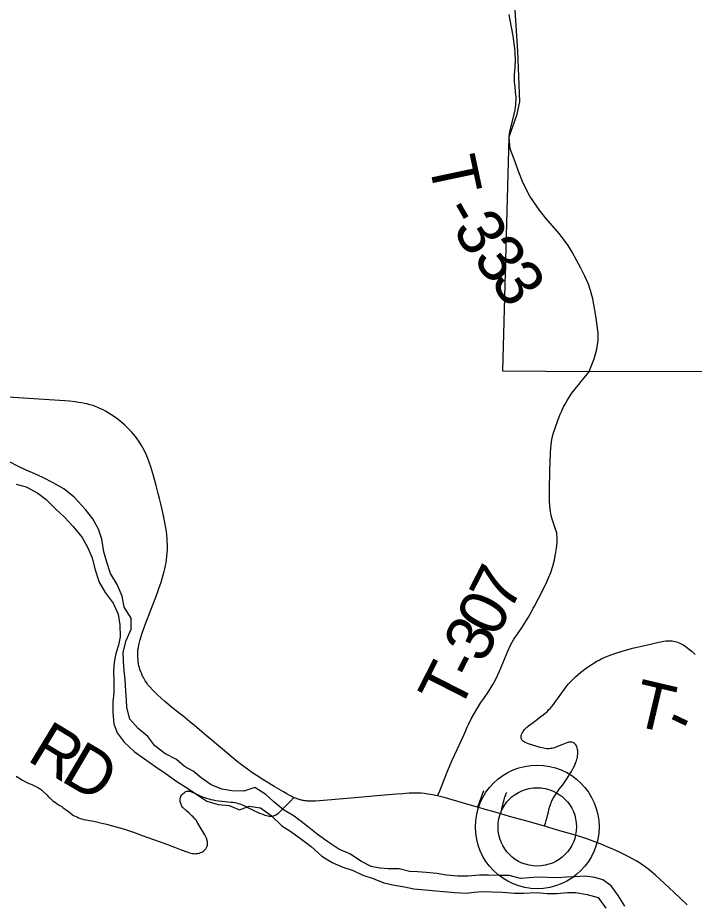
# Model space of a CAD drawing. Extents: x -10.5 to 40.6, y -3.2 to 22.
# Drawn here: x -9.859 to -9.045, y 17.758 to 18.823 of the extents above; entities that cross this region are included whole.
import ezdxf

# ---------------------------------------------------------------- set-up
doc = ezdxf.new("R2010")
doc.units = 0
for name, color, linetype in [('GM_X_Major_River', 7, 'Continuous'), ('GM_X_State_Route', 7, 'Continuous'), ('GM_X_Township_Road', 7, 'Continuous'), ('GM_X_Township_Road_Text', 7, 'Continuous'), ('GM_X_Township_Text', 7, 'Continuous'), ('GM_X_Unincorporated', 7, 'Continuous'), ('GM_X_Unincorporated_Location', 7, 'Continuous')]:
    doc.layers.add(name, color=color, linetype=linetype)

msp = doc.modelspace()

# ---------------------------------------------------------------- linework, layer by layer
at = {"layer": 'GM_X_Major_River'}
for points in [[(-9.1984, 17.7879), (-9.2086, 17.787), (-9.2215, 17.7876), (-9.2336, 17.7878), (-9.2439, 17.7869), (-9.2537, 17.7864), (-9.2674, 17.79), (-9.2776, 17.7898), (-9.2924, 17.7904), (-9.303, 17.7903), (-9.3171, 17.7889), (-9.3296, 17.7891), (-9.3428, 17.7901), (-9.3546, 17.7922), (-9.3675, 17.7936), (-9.3778, 17.7942), (-9.3873, 17.7948), (-9.3998, 17.7977), (-9.4131, 17.7979), (-9.4233, 17.7985), (-9.4336, 17.8006), (-9.4454, 17.8069), (-9.4592, 17.8158), (-9.4726, 17.8217), (-9.4859, 17.8303), (-9.4986, 17.8396), (-9.5128, 17.8508), (-9.5262, 17.8612), (-9.5392, 17.869), (-9.5507, 17.8787), (-9.5603, 17.8873), (-9.5737, 17.8958), (-9.5869, 17.8915), (-9.6013, 17.892), (-9.6134, 17.8938), (-9.6264, 17.8989), (-9.6383, 17.9075), (-9.6479, 17.9153), (-9.6585, 17.9212), (-9.6681, 17.9294), (-9.6819, 17.9368), (-9.6941, 17.9458), (-9.7026, 17.9574), (-9.7141, 17.9667), (-9.7242, 17.978), (-9.7278, 17.992), (-9.7283, 18.0014), (-9.7288, 18.012), (-9.7297, 18.0253), (-9.731, 18.0363), (-9.7319, 18.048), (-9.7321, 18.0587), (-9.7285, 18.0727), (-9.7226, 18.0865), (-9.7224, 18.0997), (-9.7309, 18.1129), (-9.7334, 18.1261), (-9.7396, 18.1401), (-9.7474, 18.1533), (-9.7517, 18.1669), (-9.7553, 18.1797), (-9.7578, 18.1948), (-9.7618, 18.2069), (-9.7688, 18.2193), (-9.7776, 18.2306), (-9.7911, 18.2452), (-9.8038, 18.2553), (-9.8164, 18.2627), (-9.829, 18.269), (-9.8385, 18.2734), (-9.8488, 18.2778), (-9.8583, 18.2822), (-9.8705, 18.2885)], [(-9.8611, 18.2609), (-9.8489, 18.2577), (-9.8348, 18.2503), (-9.8248, 18.2425), (-9.8133, 18.2309), (-9.8029, 18.2211), (-9.7925, 18.2099), (-9.7817, 18.1968), (-9.7747, 18.1844), (-9.7696, 18.1723), (-9.7664, 18.1591), (-9.7609, 18.1432), (-9.7539, 18.1304), (-9.7443, 18.1176), (-9.7384, 18.1045), (-9.7363, 18.0916), (-9.7357, 18.0772), (-9.7379, 18.0673), (-9.7411, 18.057), (-9.7429, 18.0467), (-9.7439, 18.0357), (-9.7433, 18.0225), (-9.7435, 18.0096), (-9.7445, 17.9989), (-9.7447, 17.986), (-9.7434, 17.9724), (-9.7395, 17.9618), (-9.731, 17.9502), (-9.7191, 17.939), (-9.7064, 17.9304), (-9.693, 17.9208), (-9.6804, 17.9122), (-9.6674, 17.9029), (-9.6536, 17.8944), (-9.641, 17.8858), (-9.6314, 17.8795), (-9.6177, 17.8755), (-9.6045, 17.8742), (-9.5922, 17.869), (-9.5806, 17.8734), (-9.5669, 17.8713), (-9.5539, 17.8623), (-9.5412, 17.8496), (-9.5316, 17.8437), (-9.5186, 17.8344), (-9.506, 17.8247), (-9.4929, 17.8131), (-9.4807, 17.8057), (-9.4677, 17.7998), (-9.4551, 17.7958), (-9.4437, 17.7903), (-9.4311, 17.7862), (-9.4182, 17.7811), (-9.4056, 17.7783), (-9.3935, 17.7761), (-9.3821, 17.774), (-9.3688, 17.7727), (-9.3559, 17.7713), (-9.3464, 17.7707), (-9.3327, 17.7694), (-9.3194, 17.7688), (-9.3096, 17.7697), (-9.2994, 17.7706), (-9.288, 17.7704), (-9.2755, 17.7698), (-9.261, 17.7688), (-9.2497, 17.7686), (-9.2345, 17.7696)], [(-9.1281, 17.7528), (-9.1363, 17.7656), (-9.1448, 17.7776), (-9.1547, 17.7847), (-9.1642, 17.7876), (-9.176, 17.7889), (-9.1885, 17.7884), (-9.1984, 17.7879)], [(-9.2345, 17.7696), (-9.2216, 17.7682), (-9.2099, 17.7684), (-9.1974, 17.7693), (-9.1875, 17.7694), (-9.1734, 17.767), (-9.1605, 17.7634), (-9.1512, 17.7506)]]:
    msp.add_lwpolyline(points, dxfattribs=at)
at = {"layer": 'GM_X_State_Route'}
for points in [[(-9.6496, 17.973), (-9.658, 17.9799), (-9.6721, 17.9911), (-9.682, 17.9995), (-9.6908, 18.0074), (-9.6965, 18.0128), (-9.7006, 18.0173), (-9.7024, 18.0196), (-9.7043, 18.0222), (-9.7057, 18.0242), (-9.707, 18.0265), (-9.7079, 18.0281), (-9.7088, 18.0299), (-9.7099, 18.0325), (-9.7111, 18.035), (-9.712, 18.0377), (-9.7127, 18.0401), (-9.7133, 18.0423), (-9.7137, 18.0448), (-9.714, 18.0474), (-9.7143, 18.05), (-9.7145, 18.0527), (-9.7147, 18.0561), (-9.7146, 18.0587), (-9.7144, 18.0616), (-9.7139, 18.0644), (-9.7134, 18.0675), (-9.7125, 18.0708), (-9.7116, 18.0741), (-9.7093, 18.0818), (-9.7054, 18.0929), (-9.6918, 18.1282), (-9.6891, 18.1355), (-9.6866, 18.1429), (-9.6851, 18.1475), (-9.6839, 18.1519), (-9.6829, 18.1557), (-9.682, 18.1592), (-9.6812, 18.1631), (-9.6806, 18.1663), (-9.6801, 18.17), (-9.6796, 18.1738), (-9.6793, 18.1782), (-9.679, 18.1821), (-9.6789, 18.1876), (-9.6791, 18.192), (-9.6792, 18.1945), (-9.6797, 18.2008), (-9.68, 18.2033), (-9.6804, 18.2063), (-9.6824, 18.2167), (-9.6831, 18.2204), (-9.6833, 18.2216), (-9.6839, 18.2246), (-9.6845, 18.227), (-9.6869, 18.2373), (-9.6886, 18.2439), (-9.6901, 18.2499), (-9.6925, 18.2595), (-9.6936, 18.2637), (-9.6964, 18.2739), (-9.6987, 18.2817), (-9.7008, 18.2876), (-9.7039, 18.2951), (-9.707, 18.3019), (-9.71, 18.3075), (-9.7134, 18.3127), (-9.7174, 18.3183), (-9.7196, 18.321), (-9.7219, 18.3236), (-9.7242, 18.3261), (-9.7271, 18.329), (-9.7303, 18.3321), (-9.7336, 18.3349), (-9.7359, 18.337), (-9.7384, 18.3389), (-9.7409, 18.3409), (-9.7439, 18.343), (-9.7469, 18.345), (-9.7503, 18.347), (-9.7533, 18.3488), (-9.7563, 18.3504), (-9.7593, 18.3517), (-9.762, 18.353), (-9.7655, 18.3543), (-9.7687, 18.3555), (-9.7722, 18.3565), (-9.7758, 18.3576), (-9.7788, 18.3583), (-9.7825, 18.3589), (-9.7858, 18.3595), (-9.7899, 18.3601), (-9.7967, 18.3608), (-9.8023, 18.3613), (-9.8338, 18.3633), (-9.8767, 18.3661)], [(-9.0531, 17.7547), (-9.0689, 17.7696), (-9.0808, 17.7805), (-9.0914, 17.7901), (-9.0995, 17.7969), (-9.1064, 17.8022), (-9.1104, 17.8051), (-9.1146, 17.8077), (-9.1197, 17.8105), (-9.1236, 17.8125), (-9.1283, 17.8149), (-9.1347, 17.8179), (-9.1428, 17.8215), (-9.1494, 17.8243), (-9.1567, 17.8275), (-9.1625, 17.8297), (-9.1675, 17.8316), (-9.1738, 17.8339), (-9.1812, 17.8364), (-9.1931, 17.8399), (-9.2008, 17.8422), (-9.2144, 17.8462), (-9.2249, 17.8491), (-9.2429, 17.8543), (-9.2671, 17.8611), (-9.2777, 17.8642), (-9.2805, 17.865), (-9.2871, 17.8669), (-9.2963, 17.8695), (-9.304, 17.8717), (-9.3056, 17.8721), (-9.3213, 17.8765), (-9.344, 17.8832), (-9.3489, 17.8846), (-9.3536, 17.8856), (-9.3578, 17.8865), (-9.3616, 17.8873), (-9.3654, 17.8879), (-9.3697, 17.8884), (-9.3736, 17.8888), (-9.3764, 17.889), (-9.3786, 17.889), (-9.3832, 17.889), (-9.3877, 17.8889), (-9.3917, 17.8886), (-9.3956, 17.8883), (-9.4033, 17.8876), (-9.4268, 17.8856), (-9.4534, 17.8835), (-9.472, 17.8818), (-9.4862, 17.8805), (-9.5008, 17.8793), (-9.5037, 17.8793), (-9.506, 17.8792), (-9.5081, 17.8793), (-9.5101, 17.8795), (-9.5116, 17.8796), (-9.5133, 17.8798), (-9.5149, 17.88), (-9.5156, 17.8802), (-9.5164, 17.8803), (-9.5173, 17.8805), (-9.5183, 17.8808), (-9.5193, 17.8811), (-9.5204, 17.8814), (-9.5215, 17.8818), (-9.5226, 17.8822), (-9.5236, 17.8825), (-9.5247, 17.8829), (-9.5259, 17.8834), (-9.5269, 17.8838), (-9.5286, 17.8845), (-9.5301, 17.8852), (-9.5323, 17.8864), (-9.5352, 17.888), (-9.5392, 17.8904), (-9.5505, 17.8971), (-9.5569, 17.901), (-9.5627, 17.9046), (-9.5708, 17.9098), (-9.5771, 17.914), (-9.5826, 17.9178), (-9.5897, 17.9231), (-9.595, 17.9272), (-9.5996, 17.931), (-9.6128, 17.9419), (-9.6322, 17.9585), (-9.6489, 17.9724), (-9.6496, 17.973)]]:
    msp.add_lwpolyline(points, dxfattribs=at)
at = {"layer": 'GM_X_Township_Road'}
for points in [[(-9.2675, 18.6784), (-9.2669, 18.6834), (-9.2659, 18.6882), (-9.2649, 18.6924), (-9.264, 18.6965), (-9.2617, 18.7049), (-9.2603, 18.7116), (-9.2598, 18.7147), (-9.2595, 18.7178), (-9.2593, 18.7205), (-9.2591, 18.7233), (-9.2592, 18.7277), (-9.2597, 18.732), (-9.26, 18.7351), (-9.2608, 18.7425), (-9.261, 18.745), (-9.261, 18.7478), (-9.261, 18.7499), (-9.261, 18.7519), (-9.261, 18.754), (-9.2607, 18.758), (-9.2603, 18.7629), (-9.2602, 18.7647), (-9.2601, 18.7665), (-9.26, 18.7687), (-9.26, 18.7708), (-9.2599, 18.7729), (-9.26, 18.7746), (-9.2602, 18.7776), (-9.2602, 18.7788), (-9.2604, 18.7818), (-9.2607, 18.7854), (-9.261, 18.7879), (-9.2615, 18.792), (-9.2617, 18.7944), (-9.2623, 18.7978), (-9.2628, 18.8007), (-9.2643, 18.8091), (-9.2662, 18.8197), (-9.2675, 18.8265)], [(-9.1717, 18.396), (-9.1653, 18.4119), (-9.162, 18.4234), (-9.1603, 18.4343), (-9.1603, 18.4433), (-9.1631, 18.4637), (-9.1669, 18.484), (-9.1696, 18.4943), (-9.1721, 18.5018), (-9.1762, 18.5112), (-9.1813, 18.5212), (-9.1915, 18.5401), (-9.1963, 18.5482), (-9.2007, 18.5545), (-9.2074, 18.5629), (-9.2236, 18.5818), (-9.2308, 18.5908), (-9.2424, 18.6079), (-9.2508, 18.6232), (-9.2568, 18.6388), (-9.2604, 18.649), (-9.2663, 18.6646), (-9.2675, 18.6784)], [(-9.3536, 17.8856), (-9.3511, 17.8919), (-9.3417, 17.9153), (-9.336, 17.9287), (-9.3302, 17.9416), (-9.3222, 17.959), (-9.3197, 17.9646), (-9.3179, 17.9686), (-9.3161, 17.9725), (-9.3132, 17.9784), (-9.3052, 17.9923), (-9.3016, 17.998), (-9.298, 18.0031), (-9.292, 18.0118), (-9.2872, 18.0198), (-9.2837, 18.0262), (-9.2793, 18.0359), (-9.269, 18.0599), (-9.2654, 18.0678), (-9.2618, 18.0743), (-9.258, 18.08), (-9.252, 18.0887), (-9.2444, 18.1008), (-9.2398, 18.1088), (-9.2384, 18.1116), (-9.2371, 18.1143), (-9.2319, 18.1242), (-9.2235, 18.1408), (-9.2201, 18.1482), (-9.2175, 18.1545), (-9.215, 18.1622), (-9.2129, 18.1699), (-9.2115, 18.1766), (-9.2104, 18.184), (-9.2098, 18.1908), (-9.2096, 18.1944), (-9.2097, 18.1977), (-9.2099, 18.2003), (-9.2102, 18.2025), (-9.2107, 18.2047), (-9.2115, 18.207), (-9.2159, 18.219), (-9.217, 18.2232), (-9.2179, 18.2281), (-9.2186, 18.2343), (-9.219, 18.2417), (-9.2191, 18.2542), (-9.2186, 18.2771), (-9.2179, 18.2983), (-9.2174, 18.3051), (-9.2171, 18.3081), (-9.2164, 18.3123), (-9.2157, 18.3166), (-9.2141, 18.3226), (-9.2117, 18.3297), (-9.2087, 18.3378), (-9.2059, 18.3453), (-9.2042, 18.3494), (-9.2025, 18.3533), (-9.2002, 18.3574), (-9.1977, 18.3619), (-9.1937, 18.3681), (-9.1911, 18.3717), (-9.1889, 18.3747), (-9.1859, 18.3782), (-9.1835, 18.381), (-9.1809, 18.3844), (-9.1768, 18.3895), (-9.1717, 18.396)], [(-9.2257, 17.9431), (-9.23, 17.944), (-9.2366, 17.9458), (-9.2428, 17.9478), (-9.2462, 17.9491), (-9.2483, 17.9501), (-9.2493, 17.9506), (-9.2502, 17.9512), (-9.251, 17.9519), (-9.2517, 17.9526), (-9.2522, 17.9533), (-9.2526, 17.9542), (-9.2529, 17.955), (-9.2531, 17.956), (-9.2532, 17.9568), (-9.253, 17.9578), (-9.2525, 17.9596), (-9.2519, 17.9611), (-9.2511, 17.9624), (-9.2505, 17.9634), (-9.2497, 17.9644), (-9.2489, 17.9655), (-9.2477, 17.9668), (-9.2461, 17.9683), (-9.2441, 17.9701), (-9.2401, 17.973), (-9.2348, 17.9769), (-9.2293, 17.9811), (-9.2266, 17.9832), (-9.224, 17.9854), (-9.2219, 17.9871), (-9.22, 17.9892), (-9.2181, 17.9911), (-9.2163, 17.9933), (-9.2143, 17.9957), (-9.2124, 17.9981), (-9.2008, 18.0142), (-9.1963, 18.0201), (-9.1921, 18.0247), (-9.1876, 18.0289), (-9.1811, 18.0345), (-9.1733, 18.0406), (-9.1677, 18.0444), (-9.1619, 18.0479), (-9.1592, 18.0493), (-9.1559, 18.051), (-9.1491, 18.054), (-9.1404, 18.0572), (-9.1315, 18.06), (-9.119, 18.0634), (-9.1027, 18.0673), (-9.0872, 18.0709), (-9.0811, 18.0721), (-9.0789, 18.0723), (-9.0768, 18.0724), (-9.0751, 18.0725), (-9.0731, 18.0724), (-9.0714, 18.0722), (-9.0695, 18.0719), (-9.0679, 18.0715), (-9.0659, 18.071), (-9.0639, 18.0703), (-9.0619, 18.0695), (-9.0598, 18.0685), (-9.0581, 18.0674), (-9.0561, 18.0663), (-9.0539, 18.0648), (-9.0505, 18.0621), (-9.0472, 18.0594), (-9.0434, 18.0561)], [(-9.2249, 17.8491), (-9.2237, 17.8529), (-9.2229, 17.8561), (-9.2219, 17.8599), (-9.221, 17.8636), (-9.2203, 17.8665), (-9.2197, 17.8686), (-9.2188, 17.872), (-9.2181, 17.8741), (-9.2173, 17.8764), (-9.2166, 17.8783), (-9.216, 17.8797), (-9.2154, 17.881), (-9.2148, 17.8822), (-9.2141, 17.8832), (-9.2134, 17.8844), (-9.2124, 17.8859), (-9.2116, 17.8871), (-9.2105, 17.8888), (-9.2085, 17.8917), (-9.2071, 17.8937), (-9.203, 17.8992), (-9.1987, 17.9052), (-9.1972, 17.9074), (-9.1959, 17.9094), (-9.1943, 17.9121), (-9.1926, 17.9151), (-9.1906, 17.9189), (-9.189, 17.9219), (-9.188, 17.924), (-9.1871, 17.9262), (-9.1864, 17.9281), (-9.1859, 17.9302), (-9.1854, 17.9321), (-9.1851, 17.9342), (-9.1848, 17.9359), (-9.1848, 17.9378), (-9.1848, 17.9389), (-9.1849, 17.9402), (-9.1852, 17.9417), (-9.1855, 17.9432), (-9.1859, 17.9447), (-9.1864, 17.9461), (-9.1871, 17.947), (-9.1879, 17.948), (-9.1888, 17.9488), (-9.1899, 17.9495), (-9.1908, 17.95), (-9.1919, 17.9503), (-9.193, 17.9505), (-9.1944, 17.9504), (-9.1957, 17.9502), (-9.1969, 17.95), (-9.1982, 17.9495), (-9.2022, 17.948), (-9.2113, 17.9442), (-9.2131, 17.9435), (-9.2148, 17.9431), (-9.2163, 17.9428), (-9.2178, 17.9426), (-9.2192, 17.9424), (-9.2209, 17.9424), (-9.2222, 17.9425), (-9.224, 17.9427), (-9.2257, 17.9431)], [(-9.8612, 17.9094), (-9.8578, 17.9074), (-9.8534, 17.9048), (-9.8496, 17.9027), (-9.8474, 17.9016), (-9.8457, 17.9007), (-9.8441, 17.9001), (-9.8423, 17.8993), (-9.8396, 17.8981), (-9.8367, 17.8967), (-9.8348, 17.8957), (-9.8329, 17.8946), (-9.8317, 17.8937), (-9.8307, 17.893), (-9.8297, 17.8922), (-9.8287, 17.8911), (-9.8238, 17.8864), (-9.8228, 17.8854), (-9.8216, 17.8843), (-9.8206, 17.8834), (-9.8197, 17.8824), (-9.8186, 17.8815), (-9.8177, 17.8807), (-9.8167, 17.8798), (-9.8157, 17.879), (-9.8138, 17.8776), (-9.8116, 17.8762), (-9.8104, 17.8754), (-9.8091, 17.8746), (-9.8076, 17.8737), (-9.8062, 17.8728), (-9.8048, 17.8718), (-9.8032, 17.8707), (-9.8008, 17.8689), (-9.798, 17.8668), (-9.7957, 17.8649), (-9.7937, 17.8635), (-9.7919, 17.8623), (-9.79, 17.8612), (-9.7881, 17.8603), (-9.7861, 17.8594), (-9.784, 17.8586), (-9.7821, 17.858), (-9.7797, 17.8573), (-9.7773, 17.8567), (-9.7677, 17.8551), (-9.7593, 17.8534), (-9.7521, 17.8517), (-9.7378, 17.8478), (-9.7307, 17.8457), (-9.7196, 17.842), (-9.7092, 17.8381), (-9.6888, 17.8307), (-9.679, 17.8271), (-9.6703, 17.824), (-9.6624, 17.8209), (-9.6543, 17.8179), (-9.6522, 17.8171), (-9.6505, 17.8166), (-9.6489, 17.8163), (-9.6472, 17.8162), (-9.6455, 17.8161), (-9.6442, 17.8162), (-9.6426, 17.8164), (-9.6412, 17.8166), (-9.64, 17.8169), (-9.6389, 17.8174), (-9.6377, 17.8179), (-9.6367, 17.8185), (-9.6356, 17.8192), (-9.6348, 17.82), (-9.6337, 17.8209), (-9.6327, 17.8221), (-9.6322, 17.8228), (-9.6317, 17.8236), (-9.6314, 17.8245), (-9.6311, 17.8253), (-9.6308, 17.8262), (-9.6307, 17.8271), (-9.6306, 17.8283), (-9.6306, 17.8296), (-9.6308, 17.8308), (-9.631, 17.832), (-9.632, 17.8349), (-9.6339, 17.8387), (-9.6395, 17.8481), (-9.6435, 17.855), (-9.6441, 17.856), (-9.6448, 17.8569), (-9.6455, 17.8578), (-9.6464, 17.8587), (-9.647, 17.8594), (-9.6479, 17.8603), (-9.6496, 17.8618), (-9.6529, 17.8649), (-9.6559, 17.8676), (-9.6599, 17.8714), (-9.6607, 17.8723), (-9.6614, 17.8734), (-9.662, 17.8744), (-9.6625, 17.8755), (-9.6629, 17.8765), (-9.6633, 17.8778), (-9.6635, 17.8789), (-9.6636, 17.8801), (-9.6637, 17.881), (-9.6636, 17.8819), (-9.6634, 17.8828), (-9.6632, 17.8837), (-9.6629, 17.8845), (-9.6626, 17.8853), (-9.6616, 17.8869), (-9.6604, 17.8882), (-9.6589, 17.8894), (-9.6575, 17.8904), (-9.6567, 17.8909), (-9.6558, 17.8912), (-9.6549, 17.8914), (-9.654, 17.8915), (-9.6521, 17.8913), (-9.6498, 17.8906), (-9.6413, 17.8867), (-9.6377, 17.8851), (-9.6344, 17.8839), (-9.6317, 17.883), (-9.6291, 17.8822), (-9.6266, 17.8814), (-9.6237, 17.8808), (-9.6211, 17.8803), (-9.6176, 17.8797), (-9.6136, 17.8793), (-9.6095, 17.8789), (-9.6027, 17.8783), (-9.6002, 17.878), (-9.5979, 17.8776), (-9.5957, 17.8772), (-9.5937, 17.8766), (-9.5916, 17.876), (-9.5896, 17.8753), (-9.5879, 17.8746), (-9.5862, 17.8738), (-9.5849, 17.8732), (-9.5834, 17.8724), (-9.5815, 17.8715), (-9.5756, 17.8686), (-9.5689, 17.8655), (-9.5669, 17.8646), (-9.5642, 17.8636), (-9.5616, 17.8627), (-9.5596, 17.8621), (-9.558, 17.8617), (-9.5565, 17.8613), (-9.5552, 17.8612), (-9.554, 17.8612), (-9.553, 17.8613), (-9.5522, 17.8614), (-9.5512, 17.8617), (-9.5503, 17.862), (-9.5492, 17.8624), (-9.5482, 17.863), (-9.5462, 17.8643), (-9.5453, 17.865), (-9.5434, 17.8666), (-9.5398, 17.87), (-9.5355, 17.8745), (-9.5313, 17.879), (-9.5269, 17.8838)], [(-9.3056, 17.8721), (-9.304, 17.8759), (-9.3028, 17.8791), (-9.298, 17.8923)], [(-9.2777, 17.8642), (-9.2773, 17.8663), (-9.2769, 17.8682), (-9.2765, 17.8699), (-9.2759, 17.8725), (-9.2753, 17.8747), (-9.2747, 17.8772), (-9.2741, 17.8794), (-9.2729, 17.8831), (-9.2725, 17.8844), (-9.2719, 17.8857), (-9.271, 17.8884), (-9.2703, 17.8902)]]:
    msp.add_lwpolyline(points, dxfattribs=at)
at = {"layer": 'GM_X_Township_Text'}
msp.add_lwpolyline([(-10.5445, 19.4241), (-9.8621, 19.4152), (-9.3297, 19.4093), (-9.2736, 19.4089), (-9.2734, 18.9532), (-9.2666, 18.9242), (-9.2573, 18.7823), (-9.2552, 18.7211), (-9.2586, 18.705), (-9.2677, 18.6789), (-9.2756, 18.3974), (-9.1719, 18.3965), (-8.6421, 18.3977), (-8.2403, 18.3894), (-8.2411, 17.9704), (-8.2441, 17.4134), (-7.9861, 17.4086), (-7.6509, 17.4026), (-7.3241, 17.3974), (-6.9004, 17.4016), (-6.4692, 17.3961), (-6.192, 17.3965), (-6.1874, 16.891), (-6.062, 16.8858)], dxfattribs=at)
at = {"layer": 'GM_X_Unincorporated'}
for radius in [0.0744, 0.0472]:
    msp.add_circle((-9.2337, 17.8484), radius, dxfattribs=at)
at = {"layer": 'GM_X_Unincorporated_Location'}
msp.add_line((-9.2337, 17.8484), (-9.2337, 17.8484), dxfattribs=at)

# ---------------------------------------------------------------- texts
at = {"layer": 'GM_X_Township_Road_Text'}
for s, rotation, p in [('T', 281.9706, (-9.3649, 18.6496)), ('-', 299.8915, (-9.3492, 18.59)), ('3', 301.8826, (-9.3365, 18.5679)), ('3', 310.2199, (-9.3127, 18.5309)), ('3', 303.6814, (-9.2911, 18.5056)), ('7', 63.0248, (-9.267, 18.1056)), ('0', 62.9781, (-9.2828, 18.0747)), ('3', 62.9755, (-9.2986, 18.0437)), ('-', 62.9755, (-9.3091, 18.0231)), ('T', 62.9755, (-9.3284, 17.9853)), ('T', 346.7381, (-9.1212, 17.9714)), ('-', 334.3427, (-9.0829, 17.9627)), ('R', 328.6661, (-9.8495, 17.9293)), ('D', 329.5159, (-9.8089, 17.9046))]:
    msp.add_text(s, height=0.0568, rotation=rotation, dxfattribs=at).set_placement(p)

doc.saveas('drawing.dxf')
